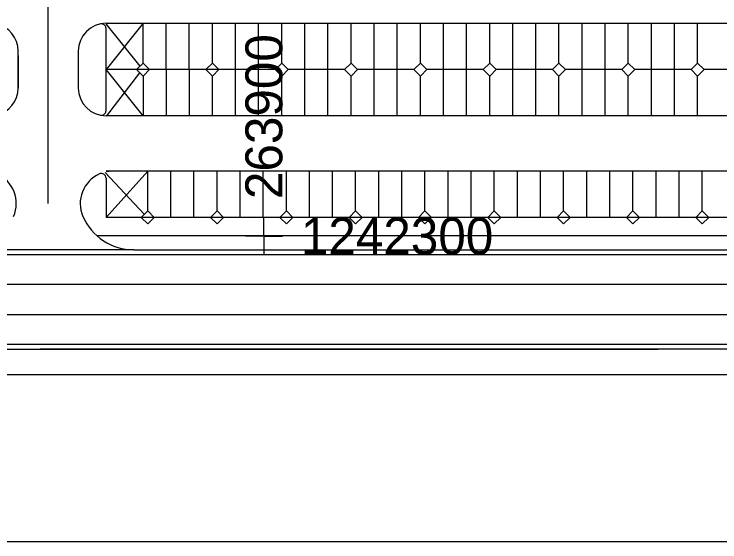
# Model space of a CAD drawing. Extents: x -264165 to -263575, y -1242333 to -1242036.
# Drawn here: x -263927 to -263850.7, y -1242333.1 to -1242276 of the extents above; entities that cross this region are included whole.
import ezdxf

# ---------------------------------------------------------------- set-up
doc = ezdxf.new("R2010")
doc.units = 0
for name, color, linetype in [('KFA_HEKT_SIET_1-1000', 7, 'Continuous'), ('KFA_SITUACIA_DRS_VYTYCOVAK_SEDA', 7, 'Continuous'), ('RAM_NA_TLAC', 7, 'Continuous')]:
    doc.layers.add(name, color=color, linetype=linetype)

msp = doc.modelspace()

# ---------------------------------------------------------------- linework, layer by layer
at = {"layer": 'KFA_HEKT_SIET_1-1000'}
for q in [(-263900, -1242298), (-263902, -1242300), (-263898, -1242300), (-263900, -1242302)]:
    msp.add_line((-263900, -1242300), q, dxfattribs=at)
at = {"layer": 'KFA_SITUACIA_DRS_VYTYCOVAK_SEDA'}
for p, q in [((-263923.33, -1242296.482), (-263923.33, -1242254.982)), ((-263918.756, -1242277.494), (-263919.208, -1242277.867)), ((-263918.24, -1242277.216), (-263918.756, -1242277.494)), ((-263917.68, -1242277.043), (-263918.24, -1242277.216)), ((-263917.08, -1242276.982), (-263917.68, -1242277.043)), ((-263917.592, -1242277.033), (-263917.68, -1242277.043)), ((-263917.504, -1242277.039), (-263917.592, -1242277.033)), ((-263917.418, -1242277.06), (-263917.504, -1242277.039)), ((-263917.337, -1242277.096), (-263917.418, -1242277.06)), ((-263917.264, -1242277.145), (-263917.337, -1242277.096)), ((-263917.201, -1242277.207), (-263917.264, -1242277.145)), ((-263917.149, -1242277.279), (-263917.201, -1242277.207)), ((-263917.111, -1242277.359), (-263917.149, -1242277.279)), ((-263917.088, -1242277.445), (-263917.111, -1242277.359)), ((-263917.08, -1242277.533), (-263917.088, -1242277.445)), ((-263917.087, -1242277.033), (-263913.421, -1242281.629)), ((-263913.068, -1242276.982), (-263917.08, -1242281.982)), ((-263917.08, -1242276.982), (-263817.068, -1242276.982)), ((-263917.08, -1242286.432), (-263917.08, -1242277.533)), ((-263913.068, -1242281.275), (-263913.068, -1242276.982)), ((-263910.568, -1242281.982), (-263910.568, -1242276.982)), ((-263908.068, -1242281.982), (-263908.068, -1242276.982)), ((-263905.568, -1242281.275), (-263905.568, -1242276.982)), ((-263903.068, -1242281.982), (-263903.068, -1242276.982)), ((-263900.568, -1242281.982), (-263900.568, -1242276.982)), ((-263898.068, -1242281.275), (-263898.068, -1242276.982)), ((-263895.568, -1242281.982), (-263895.568, -1242276.982)), ((-263893.068, -1242281.982), (-263893.068, -1242276.982)), ((-263890.568, -1242281.275), (-263890.568, -1242276.982)), ((-263888.068, -1242281.982), (-263888.068, -1242276.982)), ((-263885.568, -1242281.982), (-263885.568, -1242276.982)), ((-263883.068, -1242281.275), (-263883.068, -1242276.982)), ((-263880.568, -1242281.982), (-263880.568, -1242276.982)), ((-263878.068, -1242281.982), (-263878.068, -1242276.982)), ((-263875.568, -1242281.275), (-263875.568, -1242276.982)), ((-263873.068, -1242281.982), (-263873.068, -1242276.982)), ((-263870.568, -1242281.982), (-263870.568, -1242276.982)), ((-263868.068, -1242281.275), (-263868.068, -1242276.982)), ((-263865.568, -1242281.982), (-263865.568, -1242276.982)), ((-263863.068, -1242281.982), (-263863.068, -1242276.982)), ((-263860.568, -1242281.275), (-263860.568, -1242276.982)), ((-263858.068, -1242281.982), (-263858.068, -1242276.982)), ((-263855.568, -1242281.982), (-263855.568, -1242276.982)), ((-263853.068, -1242281.275), (-263853.068, -1242276.982)), ((-263919.578, -1242278.321), (-263919.854, -1242278.838)), ((-263919.208, -1242277.867), (-263919.578, -1242278.321)), ((-263919.854, -1242278.838), (-263920.023, -1242279.399)), ((-263920.023, -1242279.399), (-263920.08, -1242279.982)), ((-263926.58, -1242283.982), (-263926.58, -1242279.982)), ((-263926.58, -1242280.482), (-263926.58, -1242283.982)), ((-263920.08, -1242279.982), (-263920.08, -1242283.982)), ((-263913.775, -1242281.982), (-263913.068, -1242281.275)), ((-263913.068, -1242281.275), (-263912.361, -1242281.982)), ((-263906.275, -1242281.982), (-263905.568, -1242281.275)), ((-263905.568, -1242281.275), (-263904.861, -1242281.982)), ((-263898.775, -1242281.982), (-263898.068, -1242281.275)), ((-263898.068, -1242281.275), (-263897.361, -1242281.982)), ((-263891.275, -1242281.982), (-263890.568, -1242281.275)), ((-263891.275, -1242281.982), (-263890.568, -1242281.275)), ((-263890.568, -1242281.275), (-263889.861, -1242281.982)), ((-263890.568, -1242281.275), (-263889.861, -1242281.982)), ((-263883.775, -1242281.982), (-263883.068, -1242281.275)), ((-263883.068, -1242281.275), (-263882.361, -1242281.982)), ((-263876.275, -1242281.982), (-263875.568, -1242281.275)), ((-263875.568, -1242281.275), (-263874.861, -1242281.982)), ((-263868.775, -1242281.982), (-263868.068, -1242281.275)), ((-263868.068, -1242281.275), (-263867.361, -1242281.982)), ((-263861.275, -1242281.982), (-263860.568, -1242281.275)), ((-263860.568, -1242281.275), (-263859.861, -1242281.982)), ((-263853.775, -1242281.982), (-263853.068, -1242281.275)), ((-263853.068, -1242281.275), (-263852.361, -1242281.982)), ((-263898.775, -1242281.982), (-263917.08, -1242281.982)), ((-263913.068, -1242286.982), (-263917.08, -1242281.982)), ((-263913.068, -1242282.689), (-263913.775, -1242281.982)), ((-263912.361, -1242281.982), (-263913.068, -1242282.689)), ((-263910.568, -1242281.982), (-263910.568, -1242286.982)), ((-263908.068, -1242281.982), (-263908.068, -1242286.982)), ((-263905.568, -1242282.689), (-263906.275, -1242281.982)), ((-263904.861, -1242281.982), (-263905.568, -1242282.689)), ((-263903.068, -1242286.982), (-263903.068, -1242281.982)), ((-263900.568, -1242286.982), (-263900.568, -1242281.982)), ((-263898.068, -1242282.689), (-263898.775, -1242281.982)), ((-263897.361, -1242281.982), (-263898.068, -1242282.689)), ((-263891.275, -1242281.982), (-263897.361, -1242281.982)), ((-263895.568, -1242286.982), (-263895.568, -1242281.982)), ((-263893.068, -1242286.982), (-263893.068, -1242281.982)), ((-263890.568, -1242282.689), (-263891.275, -1242281.982)), ((-263890.568, -1242282.689), (-263891.275, -1242281.982)), ((-263889.861, -1242281.982), (-263890.568, -1242282.689)), ((-263889.861, -1242281.982), (-263890.568, -1242282.689)), ((-263883.775, -1242281.982), (-263889.861, -1242281.982)), ((-263888.068, -1242286.982), (-263888.068, -1242281.982)), ((-263885.568, -1242286.982), (-263885.568, -1242281.982)), ((-263883.068, -1242282.689), (-263883.775, -1242281.982)), ((-263882.361, -1242281.982), (-263883.068, -1242282.689)), ((-263876.275, -1242281.982), (-263882.361, -1242281.982)), ((-263880.568, -1242286.982), (-263880.568, -1242281.982)), ((-263878.068, -1242286.982), (-263878.068, -1242281.982)), ((-263875.568, -1242282.689), (-263876.275, -1242281.982)), ((-263874.861, -1242281.982), (-263875.568, -1242282.689)), ((-263868.775, -1242281.982), (-263874.861, -1242281.982)), ((-263873.068, -1242286.982), (-263873.068, -1242281.982)), ((-263870.568, -1242286.982), (-263870.568, -1242281.982)), ((-263868.068, -1242282.689), (-263868.775, -1242281.982)), ((-263867.361, -1242281.982), (-263868.068, -1242282.689)), ((-263861.275, -1242281.982), (-263867.361, -1242281.982)), ((-263865.568, -1242286.982), (-263865.568, -1242281.982)), ((-263863.068, -1242286.982), (-263863.068, -1242281.982)), ((-263860.568, -1242282.689), (-263861.275, -1242281.982)), ((-263859.861, -1242281.982), (-263860.568, -1242282.689)), ((-263853.775, -1242281.982), (-263859.861, -1242281.982)), ((-263858.068, -1242286.982), (-263858.068, -1242281.982)), ((-263855.568, -1242286.982), (-263855.568, -1242281.982)), ((-263853.068, -1242282.689), (-263853.775, -1242281.982)), ((-263852.361, -1242281.982), (-263853.068, -1242282.689)), ((-263846.275, -1242281.982), (-263852.361, -1242281.982)), ((-263916.984, -1242286.982), (-263913.421, -1242282.336)), ((-263913.068, -1242282.689), (-263913.068, -1242286.982)), ((-263905.568, -1242286.982), (-263905.568, -1242282.689)), ((-263898.068, -1242286.982), (-263898.068, -1242282.689)), ((-263890.568, -1242286.982), (-263890.568, -1242282.689)), ((-263883.068, -1242286.982), (-263883.068, -1242282.689)), ((-263875.568, -1242286.982), (-263875.568, -1242282.689)), ((-263868.068, -1242286.982), (-263868.068, -1242282.689)), ((-263860.568, -1242286.982), (-263860.568, -1242282.689)), ((-263853.068, -1242286.982), (-263853.068, -1242282.689)), ((-263920.08, -1242283.982), (-263920.023, -1242284.565)), ((-263920.023, -1242284.565), (-263919.854, -1242285.126)), ((-263919.854, -1242285.126), (-263919.578, -1242285.644)), ((-263919.578, -1242285.644), (-263919.208, -1242286.097)), ((-263919.208, -1242286.097), (-263918.756, -1242286.471)), ((-263918.756, -1242286.471), (-263918.24, -1242286.749)), ((-263918.24, -1242286.749), (-263917.68, -1242286.922)), ((-263917.337, -1242286.869), (-263917.264, -1242286.819)), ((-263917.264, -1242286.819), (-263917.201, -1242286.757)), ((-263917.201, -1242286.757), (-263917.149, -1242286.685)), ((-263917.149, -1242286.685), (-263917.111, -1242286.605)), ((-263917.111, -1242286.605), (-263917.088, -1242286.52)), ((-263917.088, -1242286.52), (-263917.08, -1242286.432)), ((-263917.68, -1242286.922), (-263917.08, -1242286.982)), ((-263917.68, -1242286.922), (-263917.592, -1242286.932)), ((-263917.592, -1242286.932), (-263917.504, -1242286.926)), ((-263917.504, -1242286.926), (-263917.418, -1242286.905)), ((-263917.418, -1242286.905), (-263917.337, -1242286.869)), ((-263819.568, -1242286.982), (-263917.08, -1242286.982)), ((-263917.187, -1242293.118), (-263912.937, -1242297.644)), ((-263917.08, -1242297.982), (-263912.568, -1242292.982)), ((-263817.191, -1242292.982), (-263917.08, -1242292.982)), ((-263912.568, -1242297.275), (-263912.568, -1242292.982)), ((-263910.068, -1242297.982), (-263910.068, -1242292.982)), ((-263907.568, -1242297.982), (-263907.568, -1242292.982)), ((-263905.068, -1242297.275), (-263905.068, -1242292.982)), ((-263902.568, -1242297.982), (-263902.568, -1242292.982)), ((-263900.068, -1242297.982), (-263900.068, -1242292.982)), ((-263897.568, -1242297.275), (-263897.568, -1242292.982)), ((-263895.068, -1242297.982), (-263895.068, -1242292.982)), ((-263892.568, -1242297.982), (-263892.568, -1242292.982)), ((-263890.068, -1242297.275), (-263890.068, -1242292.982)), ((-263887.568, -1242297.982), (-263887.568, -1242292.982)), ((-263885.068, -1242297.982), (-263885.068, -1242292.982)), ((-263882.568, -1242297.275), (-263882.568, -1242292.982)), ((-263880.068, -1242297.982), (-263880.068, -1242292.982)), ((-263877.568, -1242297.982), (-263877.568, -1242292.982)), ((-263875.068, -1242297.275), (-263875.068, -1242292.982)), ((-263872.568, -1242297.982), (-263872.568, -1242292.982)), ((-263870.068, -1242297.982), (-263870.068, -1242292.982)), ((-263867.568, -1242297.275), (-263867.568, -1242292.982)), ((-263865.068, -1242297.982), (-263865.068, -1242292.982)), ((-263862.568, -1242297.982), (-263862.568, -1242292.982)), ((-263860.068, -1242297.275), (-263860.068, -1242292.982)), ((-263857.568, -1242297.982), (-263857.568, -1242292.982)), ((-263855.068, -1242297.982), (-263855.068, -1242292.982)), ((-263852.568, -1242297.275), (-263852.568, -1242292.982)), ((-263917.08, -1242293.736), (-263917.08, -1242297.982)), ((-263913.275, -1242297.982), (-263912.568, -1242297.275)), ((-263912.568, -1242297.275), (-263911.861, -1242297.982)), ((-263905.775, -1242297.982), (-263905.068, -1242297.275)), ((-263905.068, -1242297.275), (-263904.361, -1242297.982)), ((-263898.275, -1242297.982), (-263897.568, -1242297.275)), ((-263897.568, -1242297.275), (-263896.861, -1242297.982)), ((-263890.775, -1242297.982), (-263890.068, -1242297.275)), ((-263890.775, -1242297.982), (-263890.068, -1242297.275)), ((-263890.068, -1242297.275), (-263889.361, -1242297.982)), ((-263890.068, -1242297.275), (-263889.361, -1242297.982)), ((-263883.275, -1242297.982), (-263882.568, -1242297.275)), ((-263882.568, -1242297.275), (-263881.861, -1242297.982)), ((-263875.775, -1242297.982), (-263875.068, -1242297.275)), ((-263875.068, -1242297.275), (-263874.361, -1242297.982)), ((-263868.275, -1242297.982), (-263867.568, -1242297.275)), ((-263867.568, -1242297.275), (-263866.861, -1242297.982)), ((-263860.775, -1242297.982), (-263860.068, -1242297.275)), ((-263860.068, -1242297.275), (-263859.361, -1242297.982)), ((-263853.275, -1242297.982), (-263852.568, -1242297.275)), ((-263852.568, -1242297.275), (-263851.861, -1242297.982)), ((-263815.601, -1242297.982), (-263917.08, -1242297.982)), ((-263912.568, -1242298.689), (-263913.275, -1242297.982)), ((-263911.861, -1242297.982), (-263912.568, -1242298.689)), ((-263905.068, -1242298.689), (-263905.775, -1242297.982)), ((-263904.361, -1242297.982), (-263905.068, -1242298.689)), ((-263897.568, -1242298.689), (-263898.275, -1242297.982)), ((-263896.861, -1242297.982), (-263897.568, -1242298.689)), ((-263890.068, -1242298.689), (-263890.775, -1242297.982)), ((-263890.068, -1242298.689), (-263890.775, -1242297.982)), ((-263889.361, -1242297.982), (-263890.068, -1242298.689)), ((-263889.361, -1242297.982), (-263890.068, -1242298.689)), ((-263882.568, -1242298.689), (-263883.275, -1242297.982)), ((-263881.861, -1242297.982), (-263882.568, -1242298.689)), ((-263875.068, -1242298.689), (-263875.775, -1242297.982)), ((-263874.361, -1242297.982), (-263875.068, -1242298.689)), ((-263867.568, -1242298.689), (-263868.275, -1242297.982)), ((-263866.861, -1242297.982), (-263867.568, -1242298.689)), ((-263860.068, -1242298.689), (-263860.775, -1242297.982)), ((-263859.361, -1242297.982), (-263860.068, -1242298.689)), ((-263852.568, -1242298.689), (-263853.275, -1242297.982)), ((-263851.861, -1242297.982), (-263852.568, -1242298.689)), ((-263816.308, -1242299.982), (-263918.049, -1242299.982)), ((-263914.08, -1242301.482), (-263932.58, -1242301.482)), ((-263932.58, -1242301.982), (-263913.841, -1242301.982)), ((-263914.08, -1242301.482), (-263815.822, -1242301.482)), ((-263913.857, -1242301.982), (-263816.374, -1242301.982)), ((-263907.131, -1242305.232), (-263975.045, -1242305.232)), ((-263832.039, -1242305.232), (-263907.131, -1242305.232)), ((-263982.828, -1242308.482), (-263877.273, -1242308.482)), ((-263877.273, -1242308.482), (-263839.344, -1242308.482)), ((-263842.662, -1242311.732), (-263980.94, -1242311.732)), ((-263980.94, -1242312.232), (-263857.327, -1242312.232)), ((-263842.601, -1242312.24), (-263924.192, -1242312.232)), ((-264038.443, -1242314.982), (-263836.403, -1242314.982))]:
    msp.add_line(p, q, dxfattribs=at)
for centre, radius, start, end in [((-263929.58, -1242279.982), 3, 0, 78.46304), ((-263929.58, -1242283.982), 3, 281.53696, 0), ((-263930.289, -1242296.482), 3.5, 336.42182, 66.24015), ((-263916.372, -1242296.482), 3.5, 113.75985, 203.57818), ((-263917.58, -1242293.736), 0.5, 0, 113.75985), ((-263916.372, -1242296.482), 3.5, 90, 101.68256), ((-263914.08, -1242295.482), 6, 203.57818, 270)]:
    msp.add_arc(centre, radius, start, end, dxfattribs=at)
at = {"layer": 'RAM_NA_TLAC'}
msp.add_lwpolyline([(-264165.158, -1242333.092), (-264165.158, -1242036.092), (-263955.158, -1242036.092), (-263575.158, -1242036.092), (-263575.158, -1242333.092), (-263955.158, -1242333.092)], close=True, dxfattribs=at)

# ---------------------------------------------------------------- texts
at = {"layer": 'KFA_HEKT_SIET_1-1000'}
msp.add_text('263900', height=4, rotation=90, dxfattribs=at).set_placement((-263898, -1242296))
msp.add_text('1242300', height=4, dxfattribs=at).set_placement((-263896, -1242302))

doc.saveas('drawing.dxf')
